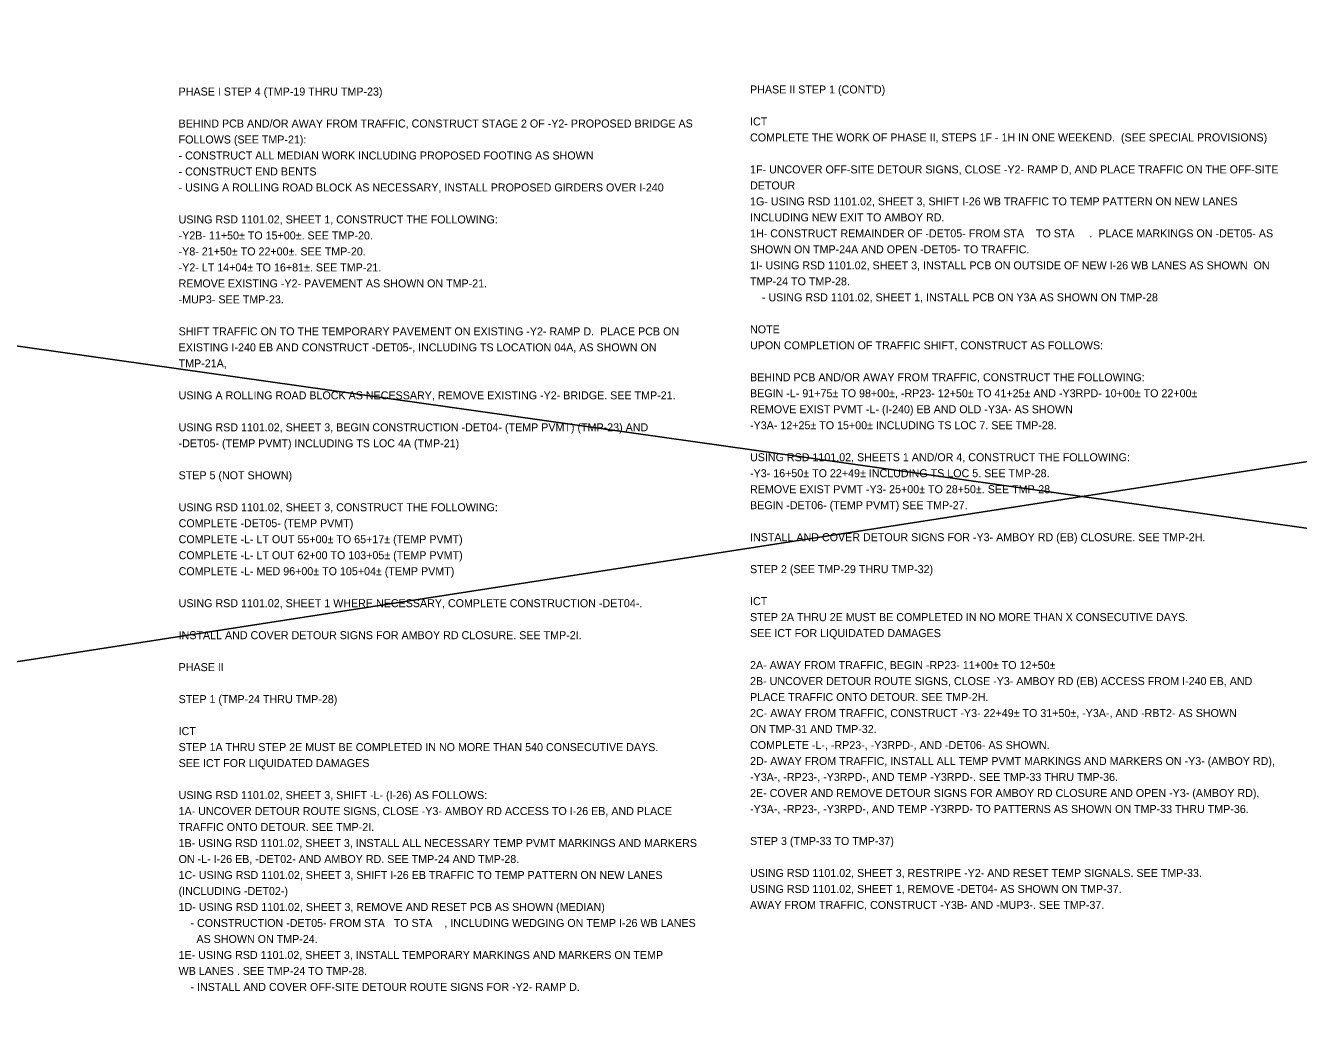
# Model space of a CAD drawing. Extents: x 2483905 to 2494512, y 366160 to 372330.
# Drawn here: x 2488905 to 2490019, y 371423 to 372296 of the extents above; entities that cross this region are included whole.
import ezdxf

# ---------------------------------------------------------------- set-up
doc = ezdxf.new("R2010")
doc.units = 0
doc.layers.add('TC SHEET BORDER LINE THIN', color=7, linetype='Continuous')

msp = doc.modelspace()

# ---------------------------------------------------------------- linework, layer by layer
at = {"layer": 'TC SHEET BORDER LINE THIN'}
for p, q in [((2486912.1, 372296.4), (2492000.8, 371577)), ((2486863.2, 371423.3), (2492035.7, 372226.5))]:
    msp.add_line(p, q, dxfattribs=at)

# ---------------------------------------------------------------- texts
for s, p in [("PHASE II STEP 1 (CONT'D)", (2489539.5, 372236.8)), ('PHASE I STEP 4 (TMP-19 THRU TMP-23)', (2489039.5, 372235)), ('BEHIND PCB AND/OR AWAY FROM TRAFFIC, CONSTRUCT STAGE 2 OF -Y2- PROPOSED BRIDGE AS', (2489039.5, 372207)), ('ICT', (2489539.5, 372208.8)), ('FOLLOWS (SEE TMP-21):', (2489039.5, 372193)), ('COMPLETE THE WORK OF PHASE II, STEPS 1F - 1H IN ONE WEEKEND.  (SEE SPECIAL PROVISIONS)', (2489539.5, 372194.8)), ('- CONSTRUCT ALL MEDIAN WORK INCLUDING PROPOSED FOOTING AS SHOWN', (2489039.5, 372179)), ('- CONSTRUCT END BENTS', (2489039.5, 372165)), ('1F- UNCOVER OFF-SITE DETOUR SIGNS, CLOSE -Y2- RAMP D, AND PLACE TRAFFIC ON THE OFF-SITE ', (2489539.5, 372166.8)), ('- USING A ROLLING ROAD BLOCK AS NECESSARY, INSTALL PROPOSED GIRDERS OVER I-240', (2489039.5, 372151)), ('DETOUR', (2489539.5, 372152.8)), ('1G- USING RSD 1101.02, SHEET 3, SHIFT I-26 WB TRAFFIC TO TEMP PATTERN ON NEW LANES', (2489539.5, 372138.8)), ('INCLUDING NEW EXIT TO AMBOY RD.', (2489539.5, 372124.8)), ('USING RSD 1101.02, SHEET 1, CONSTRUCT THE FOLLOWING:', (2489039.5, 372123)), ('-Y2B- 11+50± TO 15+00±. SEE TMP-20.', (2489039.5, 372109)), ('1H- CONSTRUCT REMAINDER OF -DET05- FROM STA    TO STA     .  PLACE MARKINGS ON -DET05- AS', (2489539.5, 372110.8)), ('-Y8- 21+50± TO 22+00±. SEE TMP-20.', (2489039.5, 372095)), ('SHOWN ON TMP-24A AND OPEN -DET05- TO TRAFFIC.', (2489539.5, 372096.8)), ('-Y2- LT 14+04± TO 16+81±. SEE TMP-21.', (2489039.5, 372081)), ('1I- USING RSD 1101.02, SHEET 3, INSTALL PCB ON OUTSIDE OF NEW I-26 WB LANES AS SHOWN  ON ', (2489539.5, 372082.8)), ('REMOVE EXISTING -Y2- PAVEMENT AS SHOWN ON TMP-21.', (2489039.5, 372067)), ('TMP-24 TO TMP-28.', (2489539.5, 372068.8)), ('-MUP3- SEE TMP-23.', (2489039.5, 372053)), ('    - USING RSD 1101.02, SHEET 1, INSTALL PCB ON Y3A AS SHOWN ON TMP-28', (2489539.5, 372054.8)), ('SHIFT TRAFFIC ON TO THE TEMPORARY PAVEMENT ON EXISTING -Y2- RAMP D.  PLACE PCB ON ', (2489039.5, 372025)), ('NOTE', (2489539.5, 372026.8)), ('EXISTING I-240 EB AND CONSTRUCT -DET05-, INCLUDING TS LOCATION 04A, AS SHOWN ON', (2489039.5, 372011)), ('UPON COMPLETION OF TRAFFIC SHIFT, CONSTRUCT AS FOLLOWS:', (2489539.5, 372012.8)), ('TMP-21A,', (2489039.5, 371997)), ('BEHIND PCB AND/OR AWAY FROM TRAFFIC, CONSTRUCT THE FOLLOWING:', (2489539.5, 371984.8)), ('USING A ROLLING ROAD BLOCK AS NECESSARY, REMOVE EXISTING -Y2- BRIDGE. SEE TMP-21.', (2489039.5, 371969)), ('BEGIN -L- 91+75± TO 98+00±, -RP23- 12+50± TO 41+25± AND -Y3RPD- 10+00± TO 22+00±', (2489539.5, 371970.8)), ('REMOVE EXIST PVMT -L- (I-240) EB AND OLD -Y3A- AS SHOWN', (2489539.5, 371956.8)), ('USING RSD 1101.02, SHEET 3, BEGIN CONSTRUCTION -DET04- (TEMP PVMT) (TMP-23) AND', (2489039.5, 371941)), ('-Y3A- 12+25± TO 15+00± INCLUDING TS LOC 7. SEE TMP-28.', (2489539.5, 371942.8)), ('-DET05- (TEMP PVMT) INCLUDING TS LOC 4A (TMP-21)', (2489039.5, 371927)), ('USING RSD 1101.02, SHEETS 1 AND/OR 4, CONSTRUCT THE FOLLOWING:', (2489539.5, 371914.8)), ('STEP 5 (NOT SHOWN)', (2489039.5, 371899)), ('-Y3- 16+50± TO 22+49± INCLUDING TS LOC 5. SEE TMP-28.', (2489539.5, 371900.8)), ('REMOVE EXIST PVMT -Y3- 25+00± TO 28+50±. SEE TMP-28.', (2489539.5, 371886.8)), ('USING RSD 1101.02, SHEET 3, CONSTRUCT THE FOLLOWING:', (2489039.5, 371871)), ('BEGIN -DET06- (TEMP PVMT) SEE TMP-27.', (2489539.5, 371872.8)), ('COMPLETE -DET05- (TEMP PVMT) ', (2489039.5, 371857)), ('COMPLETE -L- LT OUT 55+00± TO 65+17± (TEMP PVMT)', (2489039.5, 371843)), ('INSTALL AND COVER DETOUR SIGNS FOR -Y3- AMBOY RD (EB) CLOSURE. SEE TMP-2H.', (2489539.5, 371844.8)), ('COMPLETE -L- LT OUT 62+00 TO 103+05± (TEMP PVMT)', (2489039.5, 371829)), ('COMPLETE -L- MED 96+00± TO 105+04± (TEMP PVMT)', (2489039.5, 371815)), ('STEP 2 (SEE TMP-29 THRU TMP-32)', (2489539.5, 371816.8)), ('USING RSD 1101.02, SHEET 1 WHERE NECESSARY, COMPLETE CONSTRUCTION -DET04-.', (2489039.5, 371787)), ('ICT', (2489539.5, 371788.8)), ('STEP 2A THRU 2E MUST BE COMPLETED IN NO MORE THAN X CONSECUTIVE DAYS.', (2489539.5, 371774.8)), ('INSTALL AND COVER DETOUR SIGNS FOR AMBOY RD CLOSURE. SEE TMP-2I.', (2489039.5, 371759)), ('SEE ICT FOR LIQUIDATED DAMAGES', (2489539.5, 371760.8)), ('PHASE II', (2489039.5, 371731)), ('2A- AWAY FROM TRAFFIC, BEGIN -RP23- 11+00± TO 12+50±', (2489539.5, 371732.8)), ('2B- UNCOVER DETOUR ROUTE SIGNS, CLOSE -Y3- AMBOY RD (EB) ACCESS FROM I-240 EB, AND', (2489539.5, 371718.8)), ('STEP 1 (TMP-24 THRU TMP-28)', (2489039.5, 371703)), ('PLACE TRAFFIC ONTO DETOUR. SEE TMP-2H.', (2489539.5, 371704.8)), ('2C- AWAY FROM TRAFFIC, CONSTRUCT -Y3- 22+49± TO 31+50±, -Y3A-, AND -RBT2- AS SHOWN', (2489539.5, 371690.8)), ('ICT', (2489039.5, 371675)), ('ON TMP-31 AND TMP-32.', (2489539.5, 371676.8)), ('STEP 1A THRU STEP 2E MUST BE COMPLETED IN NO MORE THAN 540 CONSECUTIVE DAYS.', (2489039.5, 371661)), ('COMPLETE -L-, -RP23-, -Y3RPD-, AND -DET06- AS SHOWN.', (2489539.5, 371662.8)), ('SEE ICT FOR LIQUIDATED DAMAGES', (2489039.5, 371647)), ('2D- AWAY FROM TRAFFIC, INSTALL ALL TEMP PVMT MARKINGS AND MARKERS ON -Y3- (AMBOY RD),', (2489539.5, 371648.8)), ('-Y3A-, -RP23-, -Y3RPD-, AND TEMP -Y3RPD-. SEE TMP-33 THRU TMP-36.', (2489539.5, 371634.8)), ('USING RSD 1101.02, SHEET 3, SHIFT -L- (I-26) AS FOLLOWS:', (2489039.5, 371619)), ('2E- COVER AND REMOVE DETOUR SIGNS FOR AMBOY RD CLOSURE AND OPEN -Y3- (AMBOY RD),', (2489539.5, 371620.8)), ('1A- UNCOVER DETOUR ROUTE SIGNS, CLOSE -Y3- AMBOY RD ACCESS TO I-26 EB, AND PLACE', (2489039.5, 371605)), ('-Y3A-, -RP23-, -Y3RPD-, AND TEMP -Y3RPD- TO PATTERNS AS SHOWN ON TMP-33 THRU TMP-36.', (2489539.5, 371606.8)), ('TRAFFIC ONTO DETOUR. SEE TMP-2I.', (2489039.5, 371591)), ('STEP 3 (TMP-33 TO TMP-37)', (2489539.5, 371578.8)), ('1B- USING RSD 1101.02, SHEET 3, INSTALL ALL NECESSARY TEMP PVMT MARKINGS AND MARKERS', (2489039.5, 371577)), ('ON -L- I-26 EB, -DET02- AND AMBOY RD. SEE TMP-24 AND TMP-28.', (2489039.5, 371563)), ('1C- USING RSD 1101.02, SHEET 3, SHIFT I-26 EB TRAFFIC TO TEMP PATTERN ON NEW LANES', (2489039.5, 371549)), ('USING RSD 1101.02, SHEET 3, RESTRIPE -Y2- AND RESET TEMP SIGNALS. SEE TMP-33.', (2489539.5, 371550.8)), ('(INCLUDING -DET02-)', (2489039.5, 371535)), ('USING RSD 1101.02, SHEET 1, REMOVE -DET04- AS SHOWN ON TMP-37.', (2489539.5, 371536.8)), ('1D- USING RSD 1101.02, SHEET 3, REMOVE AND RESET PCB AS SHOWN (MEDIAN)', (2489039.5, 371521)), ('AWAY FROM TRAFFIC, CONSTRUCT -Y3B- AND -MUP3-. SEE TMP-37.', (2489539.5, 371522.8)), ('    - CONSTRUCTION -DET05- FROM STA   TO STA    , INCLUDING WEDGING ON TEMP I-26 WB LANES', (2489039.5, 371507)), ('      AS SHOWN ON TMP-24.', (2489039.5, 371493)), ('1E- USING RSD 1101.02, SHEET 3, INSTALL TEMPORARY MARKINGS AND MARKERS ON TEMP', (2489039.5, 371479)), ('WB LANES . SEE TMP-24 TO TMP-28.', (2489039.5, 371465)), ('    - INSTALL AND COVER OFF-SITE DETOUR ROUTE SIGNS FOR -Y2- RAMP D.', (2489039.5, 371451))]:
    msp.add_text(s, height=7, dxfattribs=at).set_placement(p)

doc.saveas('drawing.dxf')
